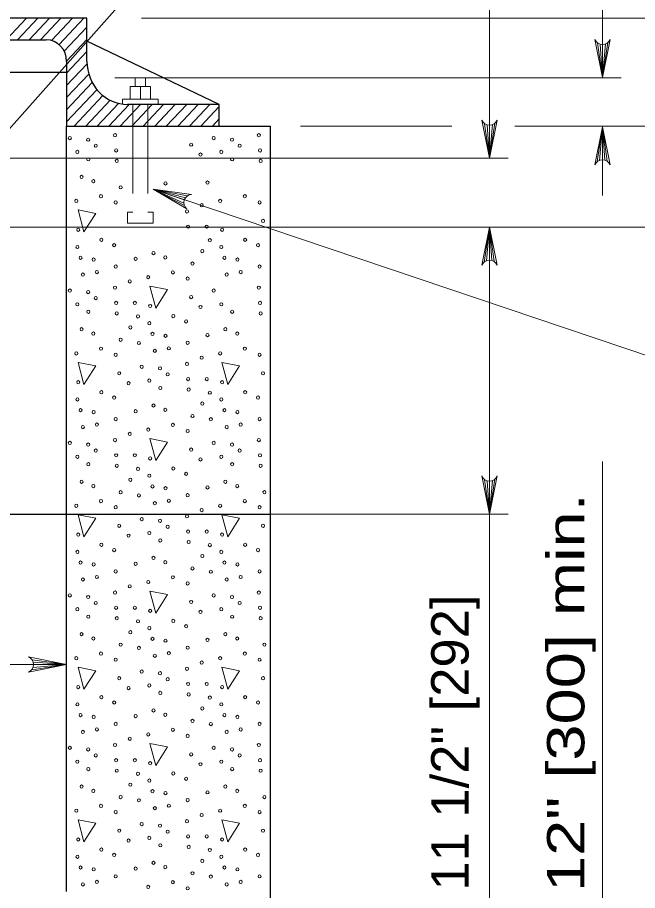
# Model space of a CAD drawing. Extents: x 1352.5 to 1386.5, y 735.9 to 779.9.
# Drawn here: x 1379.027 to 1381.616, y 772.96 to 776.602 of the extents above; entities that cross this region are included whole.
import ezdxf
from ezdxf.enums import TextEntityAlignment as Align

# ---------------------------------------------------------------- set-up
doc = ezdxf.new("R2010")
doc.units = 0
doc.header["$LTSCALE"] = 0.062
doc.linetypes.add('LONG_DASHED', pattern=[7.5, 6, -1.5])
doc.layers.add('1', color=7, linetype='Continuous', lineweight=13)

msp = doc.modelspace()

# ---------------------------------------------------------------- linework, layer by layer
at = {"layer": '1'}
for p, q in [((1378.83567, 775.96142), (1380.79, 778.15767)), ((1381.46975, 776.35067), (1381.46975, 777.71117)), ((1380.99775, 776.01483), (1380.99775, 777.68825)), ((1378.97883, 776.50908), (1379.06383, 776.599)), ((1379.02692, 776.50908), (1379.11183, 776.599)), ((1379.07492, 776.50908), (1379.15992, 776.599)), ((1379.123, 776.50908), (1379.208, 776.599)), ((1379.16825, 776.50608), (1379.25608, 776.599)), ((1379.20025, 776.48908), (1379.30408, 776.599)), ((1379.54517, 776.599), (1382.02042, 776.599)), ((1379.22192, 776.46108), (1379.31683, 776.56158)), ((1379.23183, 776.42067), (1379.31683, 776.51067)), ((1381.44958, 776.49583), (1381.46975, 776.35167)), ((1381.45958, 776.491), (1381.46975, 776.35167)), ((1381.49208, 776.49758), (1381.46975, 776.35167)), ((1381.48275, 776.492), (1381.46975, 776.35167)), ((1381.46975, 776.4895), (1381.46975, 776.35167)), ((1379.23192, 776.36983), (1379.31683, 776.45983)), ((1379.23192, 776.31908), (1379.31708, 776.40917)), ((1379.23192, 776.26817), (1379.32433, 776.366)), ((1379.43367, 776.35067), (1381.54842, 776.35067)), ((1379.51867, 776.31467), (1379.51867, 776.35067)), ((1379.51867, 776.35067), (1379.56117, 776.35067)), ((1379.56117, 776.31467), (1379.56117, 776.35067)), ((1379.23192, 776.21725), (1379.33883, 776.33042)), ((1379.49742, 776.26167), (1379.49742, 776.31467)), ((1379.49742, 776.31467), (1379.58233, 776.31467)), ((1379.53992, 776.26167), (1379.53992, 776.31467)), ((1379.58233, 776.26167), (1379.58233, 776.31467)), ((1379.23192, 776.16633), (1379.35875, 776.30067)), ((1379.26383, 776.14925), (1379.38367, 776.27608)), ((1379.31183, 776.14925), (1379.41342, 776.25675)), ((1379.36, 776.14925), (1379.44908, 776.24367)), ((1379.40808, 776.14925), (1379.49292, 776.23925)), ((1379.45617, 776.14925), (1379.541, 776.23925)), ((1379.50417, 776.14925), (1379.58908, 776.23925)), ((1379.55217, 776.14925), (1379.63708, 776.23925)), ((1379.60025, 776.14925), (1379.68517, 776.23925)), ((1379.61425, 776.23925), (1379.61425, 776.26167)), ((1379.64833, 776.14925), (1379.73325, 776.23925)), ((1379.69642, 776.14925), (1379.78133, 776.23925)), ((1379.74442, 776.14925), (1379.82942, 776.23925)), ((1379.7925, 776.14925), (1379.86908, 776.23033)), ((1379.84058, 776.14925), (1379.86908, 776.17958)), ((1381.02008, 776.16075), (1380.99775, 776.01483)), ((1380.20817, 776.14925), (1380.84017, 776.14925)), ((1380.97758, 776.15908), (1380.99775, 776.01483)), ((1380.98758, 776.15417), (1380.99775, 776.01483)), ((1381.01075, 776.15525), (1380.99775, 776.01483)), ((1380.99775, 776.15267), (1380.99775, 776.01483)), ((1381.10383, 776.14925), (1382.02042, 776.14925)), ((1381.4475, 776.00067), (1381.46975, 776.14658)), ((1381.45683, 776.00617), (1381.46975, 776.14658)), ((1381.46975, 775.85992), (1381.46975, 776.14925)), ((1381.46975, 776.00875), (1381.46975, 776.14658)), ((1381.48, 776.00725), (1381.46975, 776.14658)), ((1381.49, 776.00233), (1381.46975, 776.14658)), ((1378.38592, 776.01483), (1381.07642, 776.01483)), ((1379.72333, 775.84092), (1379.593, 775.88575)), ((1379.7215, 775.82783), (1379.593, 775.88575)), ((1379.72367, 775.81717), (1379.593, 775.88575)), ((1379.72808, 775.85008), (1379.593, 775.88575)), ((1379.73592, 775.85792), (1379.593, 775.88575)), ((1378.38592, 775.72767), (1382.02042, 775.72767)), ((1380.9755, 775.58175), (1380.99775, 775.72767)), ((1380.98483, 775.58733), (1380.99775, 775.72767)), ((1380.99775, 775.58983), (1380.99775, 775.72767)), ((1381.008, 775.58833), (1380.99775, 775.72767)), ((1381.018, 775.5835), (1380.99775, 775.72767)), ((1380.99775, 772.87267), (1380.99775, 775.72767)), ((1381.46975, 771.337), (1381.46975, 774.74983)), ((1380.97758, 774.67442), (1380.99775, 774.53017)), ((1380.98758, 774.6695), (1380.99775, 774.53017)), ((1381.02008, 774.67608), (1380.99775, 774.53017)), ((1381.01075, 774.67058), (1380.99775, 774.53017)), ((1380.99775, 774.66808), (1380.99775, 774.53017)), ((1380.0815, 774.53017), (1381.07642, 774.53017)), ((1378.34242, 773.90242), (1379.23192, 773.90242)), ((1379.086, 773.88017), (1379.23192, 773.90242)), ((1379.08767, 773.92258), (1379.23192, 773.90242)), ((1379.0915, 773.8895), (1379.23192, 773.90242)), ((1379.09258, 773.91267), (1379.23192, 773.90242)), ((1379.09408, 773.90242), (1379.23192, 773.90242))]:
    msp.add_line(p, q, dxfattribs=at)
at = {"layer": '1', "lineweight": 25}
for p, q in [((1378.46725, 776.50908), (1379.14692, 776.50908)), ((1379.86908, 776.23925), (1379.31683, 776.504)), ((1378.38233, 776.37417), (1379.23192, 776.37417)), ((1375.57867, 774.53017), (1380.0815, 774.53017))]:
    msp.add_line(p, q, dxfattribs=at)
for points in [[(1379.31683, 776.41908), (1379.31683, 776.599), (1378.46725, 776.599)], [(1379.23192, 776.41908), (1379.23192, 776.14925), (1379.86908, 776.14925), (1379.86908, 776.23925), (1379.48675, 776.23925)], [(1379.23192, 772.95608), (1379.23192, 776.14925), (1380.0815, 776.14925), (1380.0815, 772.79867), (1379.84958, 772.79867)]]:
    msp.add_lwpolyline(points, dxfattribs=at)
at = {"layer": '1'}
for points in [[(1381.50167, 776.51092), (1381.46975, 776.35167), (1381.43792, 776.51092)], [(1379.46558, 776.23925), (1379.46558, 776.26167), (1379.61425, 776.26167)], [(1381.02967, 776.17417), (1380.99775, 776.01483), (1380.96592, 776.17417)], [(1381.43792, 775.98725), (1381.46975, 776.14658), (1381.50167, 775.98725)], [(1379.73325, 775.80383), (1379.593, 775.88575), (1379.754, 775.86408)], [(1379.593, 775.88575), (1382.298, 774.97567), (1382.73225, 774.97567)], [(1380.96592, 775.56842), (1380.99775, 775.72767), (1381.02967, 775.56842)], [(1381.02967, 774.6895), (1380.99775, 774.53017), (1380.96592, 774.6895)], [(1379.07258, 773.87058), (1379.23192, 773.90242), (1379.07258, 773.93433)]]:
    msp.add_lwpolyline(points, dxfattribs=at)
at = {"layer": '1', "linetype": 'LONG_DASHED'}
for points in [[(1379.508, 776.23925), (1379.508, 775.7895), (1379.48675, 775.7895), (1379.48675, 775.7445), (1379.593, 775.7445)], [(1379.57175, 776.23925), (1379.57175, 775.7895), (1379.593, 775.7895), (1379.593, 775.7445)]]:
    msp.add_lwpolyline(points, dxfattribs=at)
at = {"layer": '1'}
for points in [[(1379.27958, 775.79942), (1379.30383, 775.70725), (1379.35333, 775.78508)], [(1379.58, 775.48142), (1379.60425, 775.38917), (1379.65375, 775.467)], [(1379.27958, 775.16333), (1379.30383, 775.07125), (1379.35333, 775.149)], [(1379.88033, 775.16333), (1379.90467, 775.07125), (1379.95408, 775.149)], [(1379.58, 774.84542), (1379.60425, 774.75317), (1379.65375, 774.831)], [(1379.27958, 774.52733), (1379.30383, 774.43517), (1379.35333, 774.51292)], [(1379.88033, 774.52733), (1379.90467, 774.43517), (1379.95408, 774.51292)], [(1379.58, 774.20933), (1379.60425, 774.11717), (1379.65375, 774.195)], [(1379.27958, 773.89133), (1379.30383, 773.79917), (1379.35333, 773.87692)], [(1379.88033, 773.89133), (1379.90467, 773.79917), (1379.95408, 773.87692)], [(1379.58, 773.57333), (1379.60425, 773.48108), (1379.65375, 773.559)], [(1379.27958, 773.25525), (1379.30383, 773.16317), (1379.35333, 773.24092)], [(1379.88033, 773.25525), (1379.90467, 773.16317), (1379.95408, 773.24092)]]:
    msp.add_lwpolyline(points, close=True, dxfattribs=at)
for centre, start, end in [((1381.46976, 776.52379), 202.08782, 337.91395), ((1380.99775, 776.18699), 202.08782, 337.91395), ((1381.46983, 775.97439), 22.08782, 157.91395), ((1379.75579, 775.82977), 93.08834, 228.91447), ((1380.99782, 775.55554), 22.08782, 157.91395), ((1380.99775, 774.70236), 202.08782, 337.91395), ((1379.05974, 773.90247), 292.08605, 67.91218)]:
    msp.add_arc(centre, 0.03438, start, end, dxfattribs=at)
at = {"layer": '1', "lineweight": 25}
for centre, major_axis, start_param, end_param in [((1379.14695, 776.41911), (0, 0.08995), 4.712389, 6.2831853), ((1379.48679, 776.41911), (0, 0.1799), 1.5707963, 3.1415927)]:
    msp.add_ellipse(centre, major_axis=major_axis, ratio=0.944544, start_param=start_param, end_param=end_param, dxfattribs=at)
at = {"layer": '1'}
for centre in [(1379.24529, 776.09909), (1379.32184, 776.09246), (1379.43403, 776.11107), (1379.84605, 776.09909), (1379.92259, 776.09246), (1380.03479, 776.11107), (1379.35373, 776.06729), (1379.43888, 776.04752), (1379.75198, 776.07158), (1379.95448, 776.06729), (1380.03964, 776.04752), (1379.27693, 776.04153), (1379.32264, 776.01031), (1379.79093, 776.03035), (1379.87769, 776.04153), (1379.92339, 776.01031), (1379.44129, 776.00374), (1380.04204, 776.00374), (1379.29425, 775.93733), (1379.34371, 775.91931), (1379.64489, 775.91008), (1379.82036, 775.91332), (1379.45726, 775.89355), (1379.27232, 775.83683), (1379.3753, 775.8566), (1379.43698, 775.83084), (1379.87308, 775.83683), (1379.97606, 775.8566), (1380.03774, 775.83084), (1379.73441, 775.79305), (1379.79598, 775.81881), (1380.05236, 775.75357), (1379.28043, 775.71662), (1379.73926, 775.7295), (1379.81716, 775.7295), (1379.88119, 775.71662), (1379.27718, 775.64449), (1379.37696, 775.67454), (1379.43047, 775.65223), (1379.83013, 775.67284), (1379.87794, 775.64449), (1379.97771, 775.67454), (1380.03123, 775.65223), (1379.59463, 775.61931), (1379.79844, 775.62731), (1379.2902, 775.59986), (1379.34451, 775.59207), (1379.51999, 775.5953), (1379.64409, 775.60129), (1379.75764, 775.57553), (1379.89095, 775.59986), (1379.94527, 775.59207), (1379.35828, 775.53975), (1379.43698, 775.56286), (1379.67568, 775.53859), (1379.95904, 775.53975), (1380.03774, 775.56286), (1379.29986, 775.52942), (1379.4956, 775.5008), (1379.5727, 775.51882), (1379.73736, 775.51283), (1379.90062, 775.52942), (1379.24529, 775.46306), (1379.43403, 775.47504), (1379.84605, 775.46306), (1380.03479, 775.47504), (1379.32184, 775.45643), (1379.35373, 775.43126), (1379.75198, 775.43555), (1379.27693, 775.4055), (1379.43888, 775.41149), (1379.51678, 775.41149), (1379.58081, 775.39861), (1379.79093, 775.39432), (1379.87769, 775.4055), (1380.03964, 775.41149), (1379.32264, 775.37428), (1379.44129, 775.36771), (1379.52975, 775.35483), (1379.67733, 775.35652), (1379.92339, 775.37428), (1380.04204, 775.36771), (1379.57756, 775.32647), (1379.73085, 775.33421), (1379.29425, 775.3013), (1379.34371, 775.28328), (1379.49806, 775.3093), (1379.59057, 775.28184), (1379.89501, 775.3013), (1379.94447, 775.28328), (1379.45726, 775.25752), (1379.53375, 775.24405), (1379.64489, 775.27405), (1379.73736, 775.24485), (1379.82036, 775.27729), (1379.3753, 775.22057), (1379.60024, 775.2114), (1379.65866, 775.22174), (1379.97606, 775.22057), (1379.27232, 775.2008), (1379.43698, 775.19481), (1379.79598, 775.18278), (1379.87308, 775.2008), (1380.03774, 775.19481), (1379.54567, 775.14505), (1379.62221, 775.13842), (1379.73441, 775.15702), (1379.4516, 775.11754), (1379.6541, 775.11324), (1380.05236, 775.11754), (1379.28043, 775.08059), (1379.49055, 775.0763), (1379.57731, 775.08748), (1379.73926, 775.09347), (1379.81716, 775.09347), (1379.88119, 775.08059), (1379.37696, 775.03851), (1379.62302, 775.05627), (1379.74167, 775.04969), (1379.83013, 775.03681), (1379.97771, 775.03851), (1379.27718, 775.00846), (1379.43047, 775.0162), (1379.79844, 774.99128), (1379.87794, 775.00846), (1380.03123, 775.0162), (1379.2902, 774.96383), (1379.34451, 774.95604), (1379.51999, 774.95927), (1379.59463, 774.98328), (1379.64409, 774.96526), (1379.89095, 774.96383), (1379.94527, 774.95604), (1379.43698, 774.92683), (1379.75764, 774.9395), (1379.83413, 774.92604), (1380.03774, 774.92683), (1379.29986, 774.89339), (1379.35828, 774.90372), (1379.5727, 774.88279), (1379.67568, 774.90256), (1379.90062, 774.89339), (1379.95904, 774.90372), (1379.4956, 774.86477), (1379.73736, 774.8768), (1379.24529, 774.82703), (1379.32184, 774.8204), (1379.43403, 774.83901), (1379.84605, 774.82703), (1379.92259, 774.8204), (1380.03479, 774.83901), (1379.27693, 774.76947), (1379.35373, 774.79523), (1379.43888, 774.77546), (1379.51678, 774.77546), (1379.75198, 774.79952), (1379.87769, 774.76947), (1379.95448, 774.79523), (1380.03964, 774.77546), (1379.32264, 774.73825), (1379.58081, 774.76258), (1379.79093, 774.75829), (1379.92339, 774.73825), (1379.44129, 774.73168), (1379.52975, 774.7188), (1379.67733, 774.7205), (1379.73085, 774.69818), (1380.04204, 774.73168), (1379.29425, 774.66527), (1379.49806, 774.67327), (1379.57756, 774.69044), (1379.89501, 774.66527), (1379.34371, 774.64725), (1379.59057, 774.64581), (1379.64489, 774.63802), (1379.82036, 774.64126), (1379.94447, 774.64725), (1379.45726, 774.62149), (1379.53375, 774.60802), (1379.73736, 774.60882), (1380.05801, 774.62149), (1379.27232, 774.56477), (1379.3753, 774.58454), (1379.43698, 774.55878), (1379.60024, 774.57537), (1379.65866, 774.58571), (1379.87308, 774.56477), (1379.97606, 774.58454), (1380.03774, 774.55878), (1379.73441, 774.52099), (1379.79598, 774.54675), (1379.4516, 774.48151), (1379.54567, 774.50902), (1379.62221, 774.50239), (1380.05236, 774.48151), (1379.28043, 774.44456), (1379.57731, 774.45145), (1379.6541, 774.47721), (1379.73926, 774.45744), (1379.81716, 774.45744), (1379.88119, 774.44456), (1379.49055, 774.44027), (1379.62302, 774.42024), (1379.74167, 774.41366), (1379.27718, 774.37243), (1379.37696, 774.40248), (1379.43047, 774.38017), (1379.83013, 774.40078), (1379.87794, 774.37243), (1379.97771, 774.40248), (1380.03123, 774.38017), (1379.59463, 774.34725), (1379.79844, 774.35526), (1379.2902, 774.3278), (1379.34451, 774.32001), (1379.51999, 774.32324), (1379.64409, 774.32923), (1379.75764, 774.30347), (1379.89095, 774.3278), (1379.94527, 774.32001), (1379.35828, 774.2677), (1379.43698, 774.2908), (1379.67568, 774.26653), (1379.83413, 774.29001), (1379.95904, 774.2677), (1380.03774, 774.2908), (1379.29986, 774.25736), (1379.4956, 774.22874), (1379.5727, 774.24676), (1379.73736, 774.24077), (1379.90062, 774.25736), (1379.24529, 774.191), (1379.43403, 774.20298), (1379.84605, 774.191), (1380.03479, 774.20298), (1379.32184, 774.18438), (1379.35373, 774.1592), (1379.75198, 774.16349), (1379.92259, 774.18438), (1379.95448, 774.1592), (1379.27693, 774.13344), (1379.43888, 774.13943), (1379.51678, 774.13943), (1379.58081, 774.12655), (1379.79093, 774.12226), (1379.87769, 774.13344), (1380.03964, 774.13943), (1379.32264, 774.10222), (1379.44129, 774.09565), (1379.52975, 774.08277), (1379.67733, 774.08447), (1379.92339, 774.10222), (1380.04204, 774.09565), (1379.57756, 774.05441), (1379.73085, 774.06215), (1379.29425, 774.02924), (1379.34371, 774.01122), (1379.49806, 774.03724), (1379.59057, 774.00979), (1379.82036, 774.00523), (1379.89501, 774.02924), (1379.94447, 774.01122), (1379.45726, 773.98546), (1379.53375, 773.97199), (1379.64489, 774.00199), (1379.73736, 773.97279), (1380.05801, 773.98546), (1379.3753, 773.94851), (1379.60024, 773.93934), (1379.65866, 773.94968), (1379.97606, 773.94851), (1379.27232, 773.92874), (1379.43698, 773.92276), (1379.79598, 773.91072), (1379.87308, 773.92874), (1380.03774, 773.92276), (1379.54567, 773.87299), (1379.62221, 773.86636), (1379.73441, 773.88496), (1379.4516, 773.84548), (1379.6541, 773.84118), (1380.05236, 773.84548), (1379.28043, 773.80853), (1379.49055, 773.80424), (1379.57731, 773.81543), (1379.73926, 773.82141), (1379.81716, 773.82141), (1379.88119, 773.80853), (1379.37696, 773.76645), (1379.62302, 773.78421), (1379.74167, 773.77763), (1379.83013, 773.76475), (1379.97771, 773.76645), (1379.27718, 773.7364), (1379.43047, 773.74414), (1379.79844, 773.71923), (1379.87794, 773.7364), (1380.03123, 773.74414), (1379.2902, 773.69177), (1379.34451, 773.68398), (1379.51999, 773.68721), (1379.59463, 773.71122), (1379.64409, 773.6932), (1379.89095, 773.69177), (1379.94527, 773.68398), (1379.43698, 773.65477), (1379.75764, 773.66744), (1379.83413, 773.65398), (1380.03774, 773.65477), (1379.29986, 773.62133), (1379.35828, 773.63167), (1379.5727, 773.61073), (1379.67568, 773.6305), (1379.73736, 773.60474), (1379.90062, 773.62133), (1379.95904, 773.63167), (1379.4956, 773.59271), (1379.24529, 773.55497), (1379.32184, 773.54835), (1379.43403, 773.56695), (1379.84605, 773.55497), (1379.92259, 773.54835), (1380.03479, 773.56695), (1379.27693, 773.49741), (1379.35373, 773.52317), (1379.43888, 773.5034), (1379.51678, 773.5034), (1379.75198, 773.52746), (1379.87769, 773.49741), (1379.95448, 773.52317), (1380.03964, 773.5034), (1379.32264, 773.46619), (1379.44129, 773.45962), (1379.58081, 773.49052), (1379.79093, 773.48623), (1379.92339, 773.46619), (1380.04204, 773.45962), (1379.52975, 773.44674), (1379.67733, 773.44844), (1379.73085, 773.42612), (1379.29425, 773.39321), (1379.49806, 773.40121), (1379.57756, 773.41838), (1379.89501, 773.39321), (1379.34371, 773.37519), (1379.45726, 773.34943), (1379.59057, 773.37376), (1379.64489, 773.36596), (1379.82036, 773.3692), (1379.94447, 773.37519), (1380.05801, 773.34943), (1379.3753, 773.31248), (1379.53375, 773.33596), (1379.65866, 773.31365), (1379.73736, 773.33676), (1379.97606, 773.31248), (1379.27232, 773.29271), (1379.43698, 773.28673), (1379.60024, 773.30332), (1379.87308, 773.29271), (1380.03774, 773.28673), (1379.73441, 773.24893), (1379.79598, 773.27469), (1379.4516, 773.20945), (1379.54567, 773.23696), (1379.62221, 773.23033), (1379.6541, 773.20515), (1380.05236, 773.20945), (1379.28043, 773.17251), (1379.49055, 773.16821), (1379.57731, 773.1794), (1379.73926, 773.18538), (1379.81716, 773.18538), (1379.88119, 773.17251), (1379.37696, 773.13042), (1379.62302, 773.14818), (1379.74167, 773.1416), (1379.97771, 773.13042), (1379.27718, 773.10037), (1379.43047, 773.10811), (1379.83013, 773.12873), (1379.87794, 773.10037), (1380.03123, 773.10811), (1379.59463, 773.07519), (1379.79844, 773.0832), (1379.2902, 773.05574), (1379.34451, 773.04795), (1379.51999, 773.05118), (1379.64409, 773.05717), (1379.75764, 773.03141), (1379.89095, 773.05574), (1379.94527, 773.04795), (1379.29986, 772.9853), (1379.35828, 772.99564), (1379.43698, 773.01874), (1379.67568, 772.99447), (1379.83413, 773.01795), (1379.90062, 772.9853), (1379.95904, 772.99564), (1380.03774, 773.01874), (1379.5727, 772.9747), (1379.73736, 772.96871)]:
    msp.add_ellipse(centre, major_axis=(0, 0.0068), ratio=0.944544, dxfattribs=at)

# ---------------------------------------------------------------- texts
at = {"layer": '1', "width": 1.3}
msp.add_text('12" [300] min.', height=0.156, rotation=90, dxfattribs=at).set_placement((1381.39417, 773.78521), align=Align.CENTER)
at = {"layer": '1', "width": 1.05}
msp.add_text('11 1/2" [292]', height=0.156, rotation=90, dxfattribs=at).set_placement((1380.9105, 772.95958))

doc.saveas('drawing.dxf')
